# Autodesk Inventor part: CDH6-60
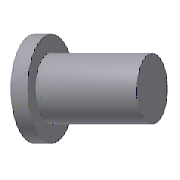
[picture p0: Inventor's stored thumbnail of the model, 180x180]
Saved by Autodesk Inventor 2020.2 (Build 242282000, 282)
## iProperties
Manager: www.cadconsulting.pl
Company: Fabian Stasiak CAD Consulting
Created: 2019-01
Part Number: CDH6-60
Material: SKD61
Description: Kołek stemplowy prosty
Document SubType Name: Modeling
Designer: F.Stasiak
Standard Revision: 1
Manufacturer: PUNCH
Language: pl-PL
Size Designation: 6-60
Categories: <MemberInstance><Categories><Category DisplayName="Forma wtryskowa" InternalName="349578f2-f4d4-4954-8c09-8e99297a61c0" Mnemonic="MOLD"><Category DisplayName="W
Mass: 1.61494 g
Surface Area: 11.4822 cm^2
Volume: 1.61494 cm^3
Density: 7.8 g/cm^3
Appearance: Aluminium — ciemne
Catalog Web Link: www.expertbooks.pl
IsCustomPart: 1
Author: F.Stasiak
Subject: Zbiór ćwiczeń. Autodesk Inventor 2020. Kurs Professional
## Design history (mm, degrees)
workplane "Work Plane1"
sketch "Sketch2"
  geometry: 2 further points
  constraints: 1 vertical alignment
  dimensions: "d21" = 2 distance of point (0, -2) point (0, 0) (= 0.5 x T_)
hole "Otwór ustalający" sketch "Sketch2" at (0, 0) diameter "d22" = 0.8 (= Anti_Rotary_D); stored, may be unused: countersink angle "d26" = 90 deg, drill point angle "d28" = 118 deg; dims "d23" = 6, "d24" = 4, "d25" = 2, "d27" = 1.2 (= 1.5 x Anti_Rotary_D)
sketch "Sketch3"
  geometry: L1 (-3.3, 3.059)-(-3.3, -3.059); A1 r 4.5 centre (0, 0) between (-3.3, 3.059) and (-3.3, -3.059) reference; 1 further point
  constraints: 2 end point, 2 point on circle, 1 vertical
  dimensions: "d29" = 3.3 distance from line of point (0, 0) L1 (= Anti_Rotary_P)
extrude "Płaszczyzna ustalająca" cut sketch "Sketch3" extent not by distance; stored distance "d30" = 10; taper "d31" = 0 deg
feature "Rzeźbienie1"
body "Solid1"
revolve "Obrót1" stored, may be unused: angle "d4" = 90 deg
fillet "Zaokrąglenie1" dims "d36" = 0.3
sketch "Sketch1"
  geometry: L1 (4.5, 0)-(4.5, 4); L2 (4.5, 4)-(3, 4); L3 (3, 4)-(3, 60); L4 (3, 60)-(0, 60); L5 (4.5, 0)-(0, 0); L6 (0, 0)-(0, 60); L7 (0, 60)-(0, -10) reference; 1 further point
  constraints: 14 end point, 2 horizontal, 1 coincident, 1 collinear, 1 parallel
  dimensions: "d2" = 4 distance of L1.start L1.end (= T_); "d19" = 60 distance between parallel lines of L4 L5 (= L); "d38" = 6 diameter of L3 L7 (= P); "d39" = 9 diameter of L1 L7 (= H_)
feature "Powierzchnia1"
body "Srf1"
other parameters: "H_" = 9 [user parameter; used in 1 equation term], "L" = 60 [user parameter; used in 1 equation term], "P" = 6 [user parameter; used in 1 equation term], "d7" = 0, "d8" = 0, "T_" = 4 [user parameter; used in 2 equation terms], "Anti_Rotary_P" = 3.3 [user parameter; used in 1 equation term], "Anti_Rotary_D" = 0.8 [user parameter; used in 2 equation terms], "d32" = 0, "d33" = 0, "d34" = 0, "d35" = 0, "IsARPlane" = 0 [user parameter], "IsARHole" = 0 [user parameter]
